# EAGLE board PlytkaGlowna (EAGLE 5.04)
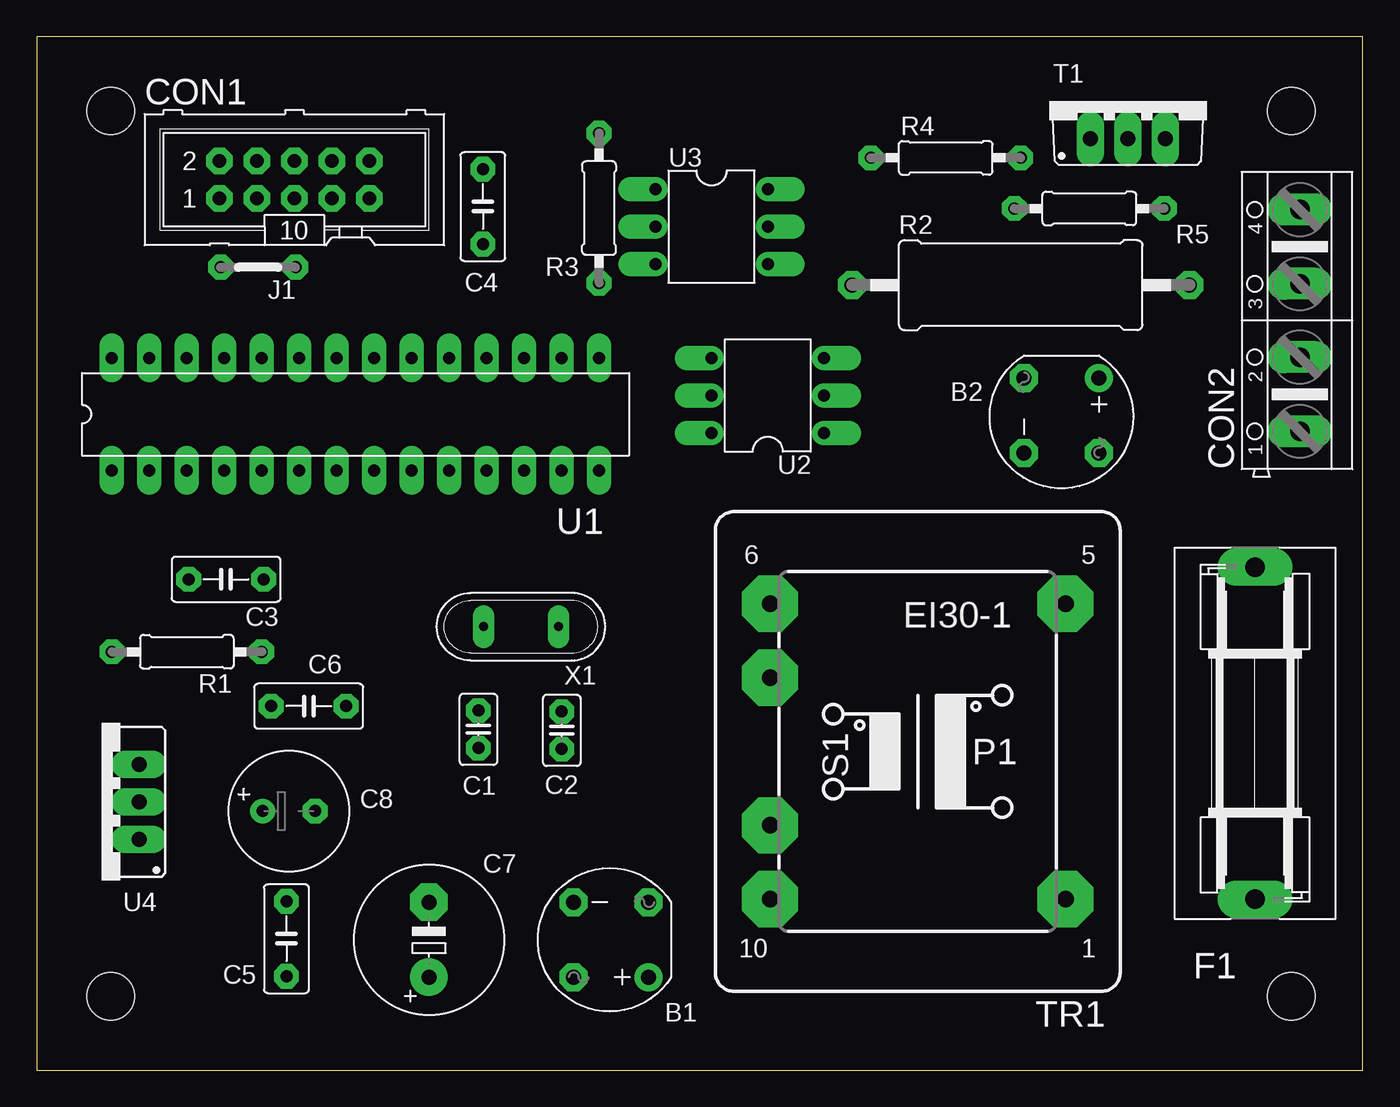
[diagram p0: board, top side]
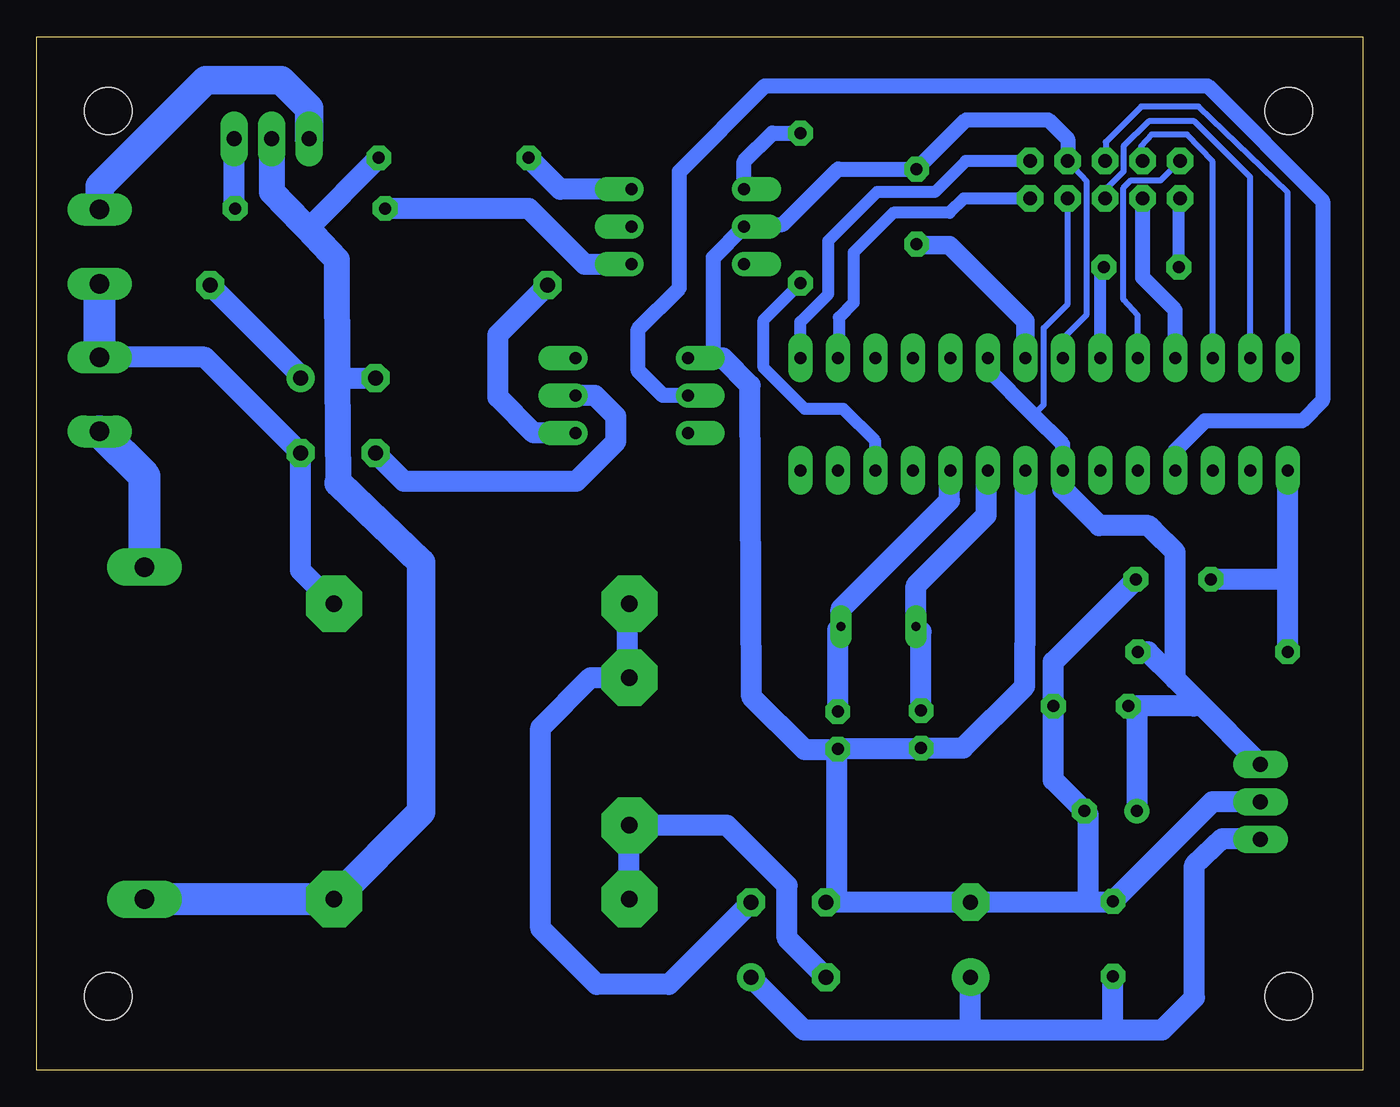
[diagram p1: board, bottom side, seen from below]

Size 89.84 x 70.02 mm. Coordinates in mm from the lower left corner, seen from the top.
Outline: 0,0 89.84,0 89.84,70.02 0,70.02 0,0
Copper layers (1*16): Top 0.035mm / dielectric 1.5mm / Bottom 0.035mm
Design rules "default *": minimum track width 10mil, minimum drill 24mil, track to track 8mil, track to pad 8mil, pad to pad 8mil, via to via 8mil, smd to smd 8mil, copper to edge 40mil, drill to drill 8mil, minimum pad ring 17mil, minimum via ring 8mil, stop-mask expansion 4mil, vias tented up to drill 0mil, thermal gap 10mil
Holes 3.2 mm at 5,65 5,5 85,5 85,65

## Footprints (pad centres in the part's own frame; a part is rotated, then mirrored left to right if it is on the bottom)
RB1A = drill 1.016 round: + -2.54,2.54 | drill 1.016 octagon: - 2.54,-2.54; AC1 2.54,2.54; AC2 -2.54,-2.54
C025-025X050 = drill 0.813 octagon: 1 -1.27,0; 2 1.27,0
C050-030X075 = drill 0.813 octagon: 1 -2.54,0; 2 2.54,0
E5-10,5 = drill 1.016 pad 2.54 round: + -2.54,0 | drill 1.016 pad 2.54 octagon: - 2.54,0
E3,5-8 = drill 0.813 pad 1.6 round: + -1.778,0 | drill 0.813 pad 1.6 octagon: - 1.778,0
ML10 = drill 0.914 octagon: 1 -5.08,-1.27; 2 -5.08,1.27; 3 -2.54,-1.27; 4 -2.54,1.27; 5 0,-1.27; 6 0,1.27; 7 2.54,-1.27; 8 2.54,1.27; 9 5.08,-1.27; 10 5.08,1.27
AK500/4 = drill 1.321 long: 1 -7.518,0; 2 -2.489,0; 3 2.489,0; 4 7.518,0
SH22,5A = drill 1.321 pad 2.54 long: 1 -11.252,0; 2 11.252,0
05 = drill 0.813 pad 1.6 octagon: 1 -2.54,0; 2 2.54,0
0207/10 = drill 0.813 octagon: 1 -5.08,0; 2 5.08,0
0617/22 = drill 1.016 octagon: 1 -11.43,0; 2 11.43,0
TO220BV = drill 1.016 long: G 2.54,-2.54; T1 -2.54,-2.54; T2 0,-2.54
EI30-1 = drill 1.118 pad 3.81 octagon: 1 -10.008,10.008; 5 -10.008,-10.008; 6 10.008,-10.008; 7 10.008,-5.004; 9 10.008,5.004; 10 10.008,10.008
DIL28-3 = drill 0.813 long: 1 -16.51,-3.81; 2 -13.97,-3.81; 3 -11.43,-3.81; 4 -8.89,-3.81; 5 -6.35,-3.81; 6 -3.81,-3.81; 7 -1.27,-3.81; 8 1.27,-3.81; 9 3.81,-3.81; 10 6.35,-3.81; 11 8.89,-3.81; 12 11.43,-3.81; 13 13.97,-3.81; 14 16.51,-3.81; 15 16.51,3.81; 16 13.97,3.81; 17 11.43,3.81; 18 8.89,3.81; 19 6.35,3.81; 20 3.81,3.81; 21 1.27,3.81; 22 -1.27,3.81; 23 -3.81,3.81; 24 -6.35,3.81; 25 -8.89,3.81; 26 -11.43,3.81; 27 -13.97,3.81; 28 -16.51,3.81
DIL06 = drill 0.813 offset: 1 -2.54,-3.81; 2 0,-3.81; 3 2.54,-3.81; 4 2.54,3.81; 5 0,3.81; 6 -2.54,3.81
78XXS = drill 1.016 long: GND 0,-2.54; IN -2.54,-2.54; OUT 2.54,-2.54
QS = drill 0.61 long: 1 -2.54,0; 2 2.54,0

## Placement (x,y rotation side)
B1  1,5A  [RB1A]  38.9,8.83 180 top
B2  1,5A  [RB1A]  69.43,44.36 270 top
C1  22pF  [C025-025X050]  29.92,23.09 270 top
C2  22pF  [C025-025X050]  35.57,23.02 270 top
C3  10nF  [C050-030X075]  12.82,33.26 180 top
C4  100nF  [C050-030X075]  30.22,58.52 90 top
C5  100nF  [C050-030X075]  16.91,8.9 90 top
C6  100nF  [C050-030X075]  18.42,24.66 0 top
C7  1000uF  [E5-10,5]  26.57,8.83 90 top
C8  220uF  [E3,5-8]  17.07,17.55 0 top
CON1  IDC10  [ML10]  17.45,60.34 0 top
CON2  ARK 2x2  [AK500/4]  85.59,50.8 90 top
F1  2A  [SH22,5A]  82.55,22.83 90 top
J1  J5MM  [05]  14.99,54.41 180 top
R1  10k  [0207/10]  10.16,28.35 180 top
R2  100k  [0617/22]  66.67,53.2 0 top
R3  560R  [0207/10]  38.1,58.42 90 top
R4  220R  [0207/10]  61.59,61.82 0 top
R5  220R  [0207/10]  71.32,58.39 0 top
T1  BT138-V  [TO220BV]  73.94,65.65 0 top
TR1  [EI30-1]  59.69,21.59 180 top
U1  MEGA8-P  [DIL28-3]  21.59,44.45 0 top
U2  CNY17  [DIL06]  49.53,45.72 90 top
U3  MOC3021M  [DIL06]  45.72,57.15 270 top
U4  LM7805  [78XXS]  4.38,18.18 90 top
X1  16MHz  [QS]  32.81,30.05 180 top

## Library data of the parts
B1 B2 = rectifier
C1-C8 R1-R5 = resistor
CON1 = con-harting-ml
CON2 = con-ptr500
F1 = fuse
J1 = jumper
T1 = triac
TR1 = trafo
U1 = avr-7
U2 U3 = optocoupler
U4 = v-reg
X1 = special

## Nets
+5V: C6.1 C8.+ CON1.7 R1.1 U1.7 U1.20 U4.OUT
GND: B1.- C3.1 C4.2 C5.2 C6.2 C7.- C8.- CON1.8 U1.22 U2.4 U3.2 U4.GND
N$1: CON1.1 J1.2
N$2: CON1.2 U1.24
N$3: CON1.3 U1.25
N$4: CON1.4 U1.26
N$5: CON1.5 U1.27
N$6: CON1.6 U1.28
N$7: CON1.9 U1.16
N$8: CON1.10 U1.15
N$9: C1.1 U1.9 X1.2
N$10: C2.1 U1.10 X1.1
N$11: C4.1 U1.21
N$12: B1.AC1 TR1.9
N$13: C3.2 R1.2 U1.1
N$14: B1.AC2 TR1.7
N$15: CON2.1 F1.2
N$16: B1.+ C5.1 C7.+ U4.IN
N$18: B2.+ R2.2
N$19: R2.1 U2.1
N$20: B2.- U2.2
N$21: R3.1 U1.12
N$22: R5.1 U3.4
N$23: R4.1 U3.6
N$24: R5.2 T1.G
N$25: B2.AC2 F1.1 R4.2 T1.T2 TR1.1
N$26: B2.AC1 CON2.2 CON2.3 TR1.5
N$27: CON2.4 T1.T1
N$28: R3.2 U3.1
N$31: C1.2 C2.2 U1.8
N$32: J1.1 U1.23
N$40: U1.4 U2.5

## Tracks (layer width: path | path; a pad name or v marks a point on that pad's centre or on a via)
+5V
  Bottom 0.254: R1.1 15.24,27.94 | 14.2,36.6 13.97,36.83
  Bottom 0.406: CON1.7 19.99,51.91 21.6,50.3 21.6,45.1 22.3,44.4
  Bottom 1.016: U1.7 20.32,42.42 22.3,44.4 25.4,47.5 U1.20
  Bottom 1.422: U4.OUT 11.15,24.95 | 11.15,24.95 12.7,26.5 | 12.7,26.5 14.55,28.35 R1.1 | 12.7,26.5 12.7,35.1 14.2,36.6 14.5,36.9 17.85,36.9 20.32,39.37 U1.7 20.3,40.66 | C8.+ 15.29,24.07 C6.1 11.44,24.66 11.15,24.95
GND
  Bottom 0.406: U1.22 20.32,49.58 18.7,51.2 18.7,60.22 CON1.8
  Bottom 1.016: 44,48.26 44,55.06 U3.2 41.76,57.3 39.3,57.3 35.54,61.06 C4.2 26.88,64.4 21.3,64.4 19.99,63.09 CON1.8
  Bottom 1.422: U2.4 44,48.26 43.36,48.26 41.5,46.4 41.4,25.3 37.8,21.7 35.62,21.7 35.62,11.69 35.3,11.37 | 35.3,11.37 C7.- 18.6,11.37 | 35.3,11.37 B1.- | 18.6,11.37 16.98,11.37 C5.2 10.17,18.18 U4.GND | 18.6,11.37 18.6,17.3 C8.- 20.96,19.66 C6.2 20.96,27.66 C3.1
N$1
  Bottom 0.813: J1.2 12.45,58.99 CON1.1
N$2
  Bottom 0.406: U1.24 15.24,51.14 16.2,52.2 16.2,59.8 15.7,60.3 13.68,60.3 CON1.2
N$3
  Bottom 1.016: U1.25 12.7,51.5 14.9,53.7 CON1.3
N$4
  Bottom 0.406: U1.26 10.16,61.56 11.9,63.4 14.3,63.4 15,62.6 15,61.7 CON1.4
N$5
  Bottom 0.406: U1.27 7.62,60.52 11.4,64.3 14.5,64.3 16.2,62.6 16.2,60.9 17.4,59.7 17.4,59.12 CON1.5
N$6
  Bottom 0.406: U1.28 5.08,59.48 11.1,65.3 15,65.3 17.4,62.9 17.4,61.66 CON1.6
N$7
  Bottom 0.813: CON1.9 27.03,59.07 28,58.1 31.8,58.1 34.5,55.4 34.5,52 35.5,51 35.5,48.32
  Bottom 1.016: 35.5,48.32 U1.16
N$8
  Bottom 0.813: U1.15 38.1,50.7 36.2,52.6 36.2,56.2 32.9,59.5 29,59.5 26.89,61.61 CON1.10
N$9
  Bottom 1.422: U1.9 25.5,40.54 25.5,37.6 30.27,32.83 X1.2 29.92,29.7 C1.1
N$10
  Bottom 1.422: U1.10 28,40.58 28,38.6 35.35,31.25 X1.1 35.57,29.83 C2.1
N$11
  Bottom 1.27: U1.21 22.86,50.76 28,55.9 30.14,55.9 C4.1
N$12
  Bottom 1.422: B1.AC1 39,8.93 39,12.5 43.09,16.59 TR1.9
N$13
  Bottom 0.254: R1.2 5.08,27.94
  Bottom 1.422: R1.2 5.08,33.1 | 5.08,33.1 U1.1 | C3.2 5.24,33.26 5.08,33.1
N$14
  Bottom 1.422: B1.AC2 47.01,5.8 51.9,5.8 55.7,9.6 55.7,23.2 52.31,26.59 TR1.7
N$15
  Bottom 2.184: F1.2 82.55,40.24 CON2.1
N$16
  Bottom 1.422: B1.+ 37.85,2.7 26.8,2.7 | 17,2.7 13.6,2.7 11.4,4.9 11.4,13.9 9.5,15.7 7.36,15.7 U4.IN | 17,2.7 26.8,2.7 | C7.+ 26.57,2.93 26.8,2.7 | C5.1 16.91,2.79 17,2.7
N$17
  Bottom 1.422: 49.8,26.7 49.8,31.7
N$18
  Bottom 1.422: B2.+ 71.97,47.07 R2.2
N$19
  Bottom 1.422: R2.1 58.6,49.84 58.6,45.6 56.18,43.18 U2.1
N$20
  Bottom 1.422: B2.- 64.97,39.9 53.3,39.9 50.6,42.6 50.6,44.3 52.02,45.72 U2.2
N$21
  Bottom 0.813: U1.12 33.02,42.62 35.2,44.8 37.8,44.8 40.6,47.6 40.6,50.84 R3.1
N$22
  Bottom 1.422: U3.4 52.7,54.6 56.49,58.39 R5.1
N$23
  Bottom 1.422: R4.1 54.38,59.69 U3.6
N$24
  Bottom 1.422: R5.2 76.48,58.47 T1.G
N$25
  Bottom 0.254: T1.T2 73.96,63.13
  Bottom 1.422: B2.AC2 69.45,46.9 | R4.2 71.42,57.07 71.53,57.07
  Bottom 1.778: 69.4,39.8 69.45,46.9 | 69.45,46.9 69.5,54.9 71.53,57.07 71.78,57.34 73.9,59.5 73.9,62.97 T1.T2 | 69.45,46.9 69.44,46.9
  Bottom 1.93: TR1.1 63.8,17.48 63.8,34.4 69.4,39.8
  Bottom 2.184: TR1.1 F1.1
N$26
  Bottom 1.422: TR1.5 71.97,33.87 B2.AC1 78.46,48.31 CON2.2
  Bottom 2.184: CON2.2 CON2.3
N$27
  Bottom 1.93: CON2.4 85.59,59.91 78.4,67.1 73.3,67.1 71.4,65.2 T1.T1
N$28
  Bottom 1.016: U3.1 41.91,61.59 40,63.5 R3.2
N$30
  Bottom 1.422: 49.7,11.5 49.7,16.7
N$31
  Bottom 1.422: C2.2 29.99,21.75 C1.2 27.08,21.82 22.9,26 22.9,28.84 22.86,28.88 U1.8
N$32
  Bottom 0.813: U1.23 17.78,54.16 J1.1
N$40
  Bottom 1.016: U2.5 47.42,45.72 49.1,47.4 49.1,50.2 46.3,53 46.3,60.9 40.5,66.7 10.5,66.7 2.7,58.9 2.7,45.4 4.1,44 10.7,44 12.7,42 U1.4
